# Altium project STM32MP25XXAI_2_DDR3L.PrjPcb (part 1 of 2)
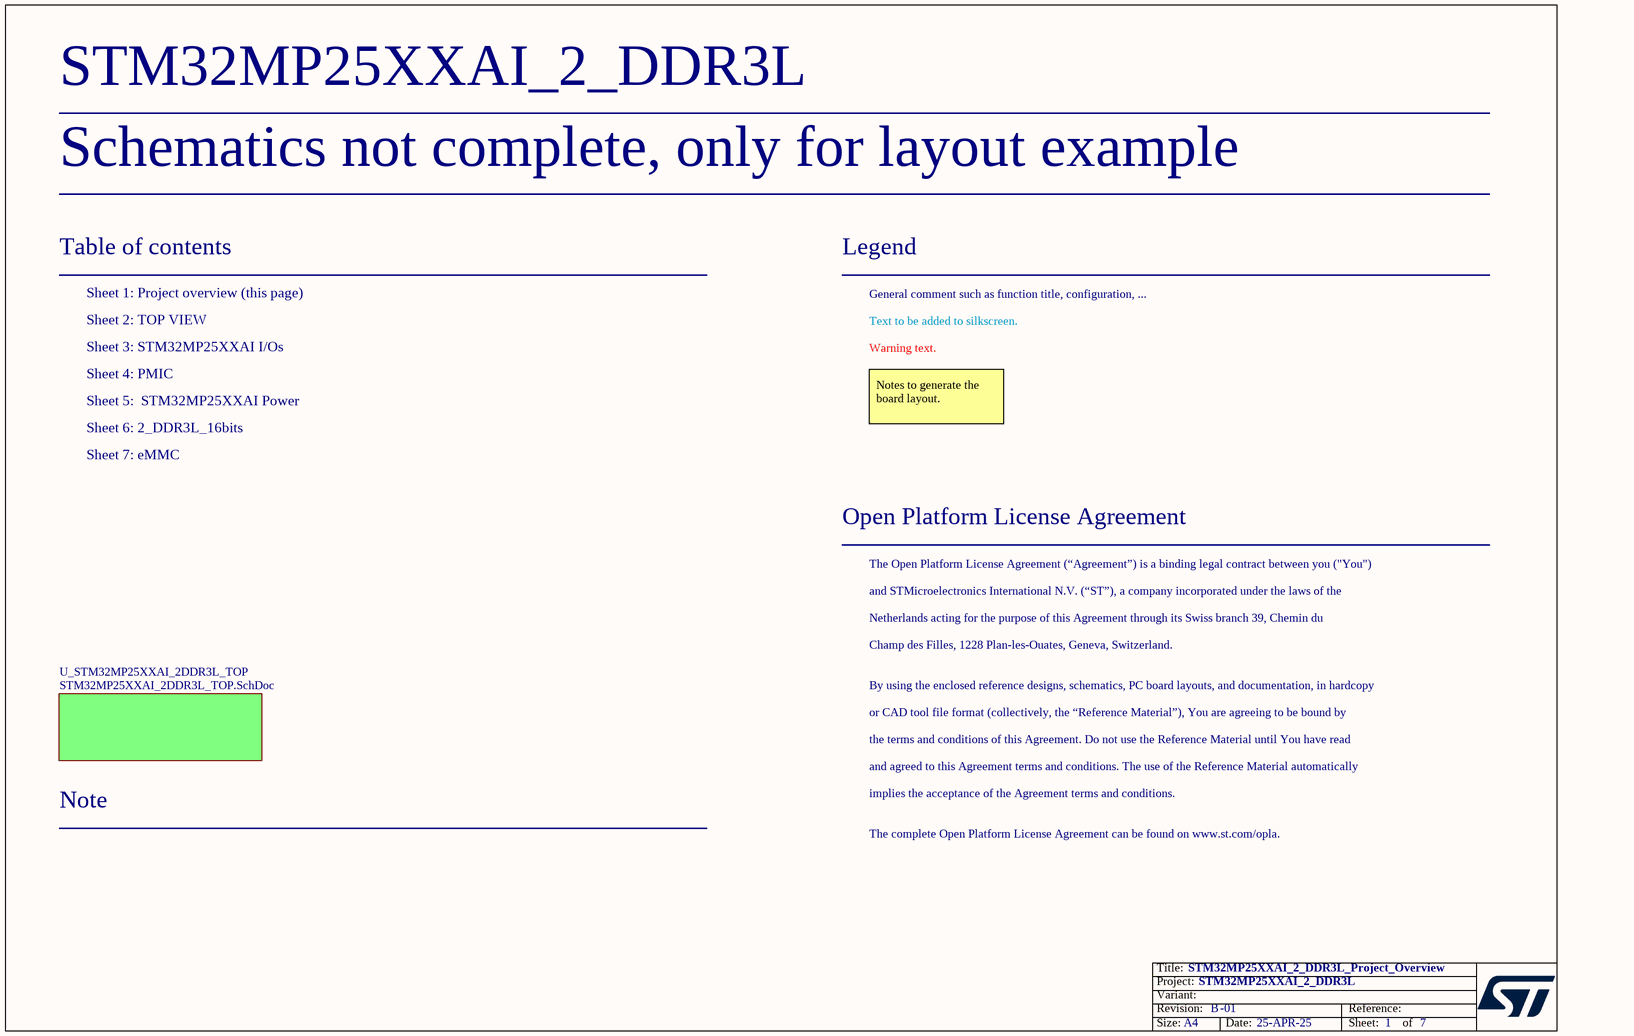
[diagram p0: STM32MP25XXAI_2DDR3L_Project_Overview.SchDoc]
Board_PCB_Revision: B; Board_Name: STM32MP25XXAI_2_DDR3L; Board_Document_Date: 25-APR-25; Board_Assembly_Revision: 01
7 sheets, 237 parts. Net scope: flat (ports and power ports of the same name join across sheets).
Board file: STM32MP25XXAI_2_DDR3L.PcbDoc
Sheets:
  STM32MP25XXAI_2DDR3L_Project_Overview.SchDoc
    U_STM32MP25XXAI_2DDR3L_TOP = STM32MP25XXAI_2DDR3L_TOP.SchDoc
      U_STM32MP25XXAI I_Os = STM32MP25XXAI I_Os.SchDoc
      U_PMIC = PMIC.SchDoc
      U_STM32MP25XXAI Power = STM32MP25XXAI Power.SchDoc
      U_eMMC = eMMC.SchDoc
      U_2_DDR3L_16bits = 2_DDR3L_16bits.SchDoc

## Sheet STM32MP25XXAI_2DDR3L_Project_Overview.SchDoc: STM32MP25XXAI_2_DDR3L_Project_Overview
size A4; Date: Not used; ApprovedBy: Not used; CheckedBy: Not used; Author: Not used; CompanyName: STMicroelectronics; DrawnBy: Not used; Engineer: Not used; Organization: Not used; Address1: Not used; Address2: Not used; Address3: Not used; Address4: Not used; DocumentNumber: 1; Revision: Not used; SheetNumber: 1; SheetTotal: 7

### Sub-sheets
U_STM32MP25XXAI_2DDR3L_TOP = STM32MP25XXAI_2DDR3L_TOP.SchDoc: no entries

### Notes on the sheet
- Schematics not complete, only for layout example
- Table of contents
- Sheet 1: Project overview (this page)
- Legend
- General comment such as function title, configuration, ...
- Sheet 2: TOP VIEW
- Sheet 3: STM32MP25XXAI I/Os
- Sheet 4: PMIC
- Text to be added to silkscreen.
- Warning text.
- Sheet 5:  STM32MP25XXAI Power
- Sheet 6: 2_DDR3L_16bits
- Notes to generate the board layout.
- Sheet 7: eMMC
- Open Platform License Agreement
- The Open Platform License Agreement (“Agreement”) is a binding legal contract between you ("You")
- and STMicroelectronics International N.V. (“ST”), a company incorporated under the laws of the
- Netherlands acting for the purpose of this Agreement through its Swiss branch 39, Chemin du
- Champ des Filles, 1228 Plan-les-Ouates, Geneva, Switzerland.
- By using the enclosed reference designs, schematics, PC board layouts, and documentation, in hardcopy
- or CAD tool file format (collectively, the “Reference Material”), You are agreeing to be bound by
- the terms and conditions of this Agreement. Do not use the Reference Material until You have read
- and agreed to this Agreement terms and conditions. The use of the Reference Material automatically
- Note
- implies the acceptance of the Agreement terms and conditions.
- The complete Open Platform License Agreement can be found on www.st.com/opla.

## Sheet STM32MP25XXAI_2DDR3L_TOP.SchDoc: TOP
size A4; Date: Not used; ApprovedBy: Not used; CheckedBy: Not used; Author: Not used; CompanyName: STMicroelectronics; DrawnBy: Not used; Engineer: Not used; Organization: Not used; Address1: Not used; Address2: Not used; Address3: Not used; Address4: Not used; DocumentNumber: 2; Revision: Not used; SheetNumber: 2; SheetTotal: 7
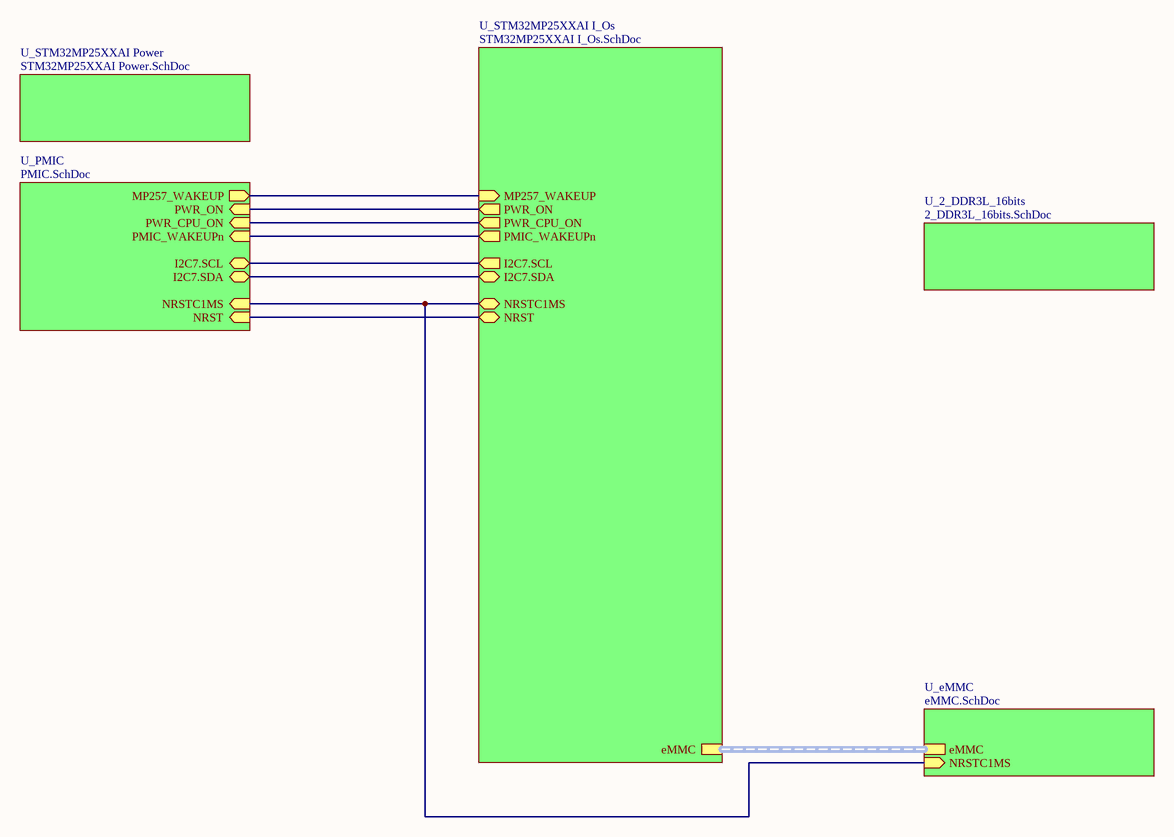
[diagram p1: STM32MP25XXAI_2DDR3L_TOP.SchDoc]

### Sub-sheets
U_2_DDR3L_16bits = 2_DDR3L_16bits.SchDoc: no entries
U_eMMC = eMMC.SchDoc: eMMC (harness eMMC), NRSTC1MS (in)
U_PMIC = PMIC.SchDoc: PMIC_WAKEUPn (in), NRST (in), I2C7.SCL (bidir), PWR_ON (in), PWR_CPU_ON (in), NRSTC1MS (in), I2C7.SDA (bidir), MP257_WAKEUP (out)
U_STM32MP25XXAI I_Os = STM32MP25XXAI I_Os.SchDoc: NRST (bidir), PWR_ON (out), NRSTC1MS (bidir), I2C7.SDA (bidir), I2C7.SCL (out), PWR_CPU_ON (out), MP257_WAKEUP (in), PMIC_WAKEUPn (out), eMMC (harness eMMC)
U_STM32MP25XXAI Power = STM32MP25XXAI Power.SchDoc: no entries

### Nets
(unnamed): sheet U_STM32MP25XXAI I_Os/NRST, sheet U_PMIC/NRST
(unnamed): sheet U_STM32MP25XXAI I_Os/PWR_ON, sheet U_PMIC/PWR_ON  [a separate net that carries the same name]
(unnamed): sheet U_STM32MP25XXAI I_Os/NRSTC1MS, sheet U_PMIC/NRSTC1MS, sheet U_eMMC/NRSTC1MS  [a separate net that carries the same name]
(unnamed): sheet U_STM32MP25XXAI I_Os/I2C7.SDA, sheet U_PMIC/I2C7.SDA  [a separate net that carries the same name]
(unnamed): sheet U_STM32MP25XXAI I_Os/I2C7.SCL, sheet U_PMIC/I2C7.SCL  [a separate net that carries the same name]
(unnamed): sheet U_STM32MP25XXAI I_Os/PWR_CPU_ON, sheet U_PMIC/PWR_CPU_ON  [a separate net that carries the same name]
(unnamed): sheet U_STM32MP25XXAI I_Os/MP257_WAKEUP, sheet U_PMIC/MP257_WAKEUP  [a separate net that carries the same name]
(unnamed): sheet U_STM32MP25XXAI I_Os/PMIC_WAKEUPn, sheet U_PMIC/PMIC_WAKEUPn  [a separate net that carries the same name]

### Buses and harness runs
harness sheet U_eMMC/eMMC = sheet U_STM32MP25XXAI I_Os/eMMC

## Sheet STM32MP25XXAI I_Os.SchDoc: STM32MP25XXAI  I/Os
size A3; Date: Not used; ApprovedBy: Not used; CheckedBy: Not used; Author: Not used; CompanyName: STMicroelectronics; DrawnBy: Not used; Engineer: Not used; Organization: Not used; Address1: Not used; Address2: Not used; Address3: Not used; Address4: Not used; DocumentNumber: 3; Revision: Not used; SheetNumber: 3; SheetTotal: 7
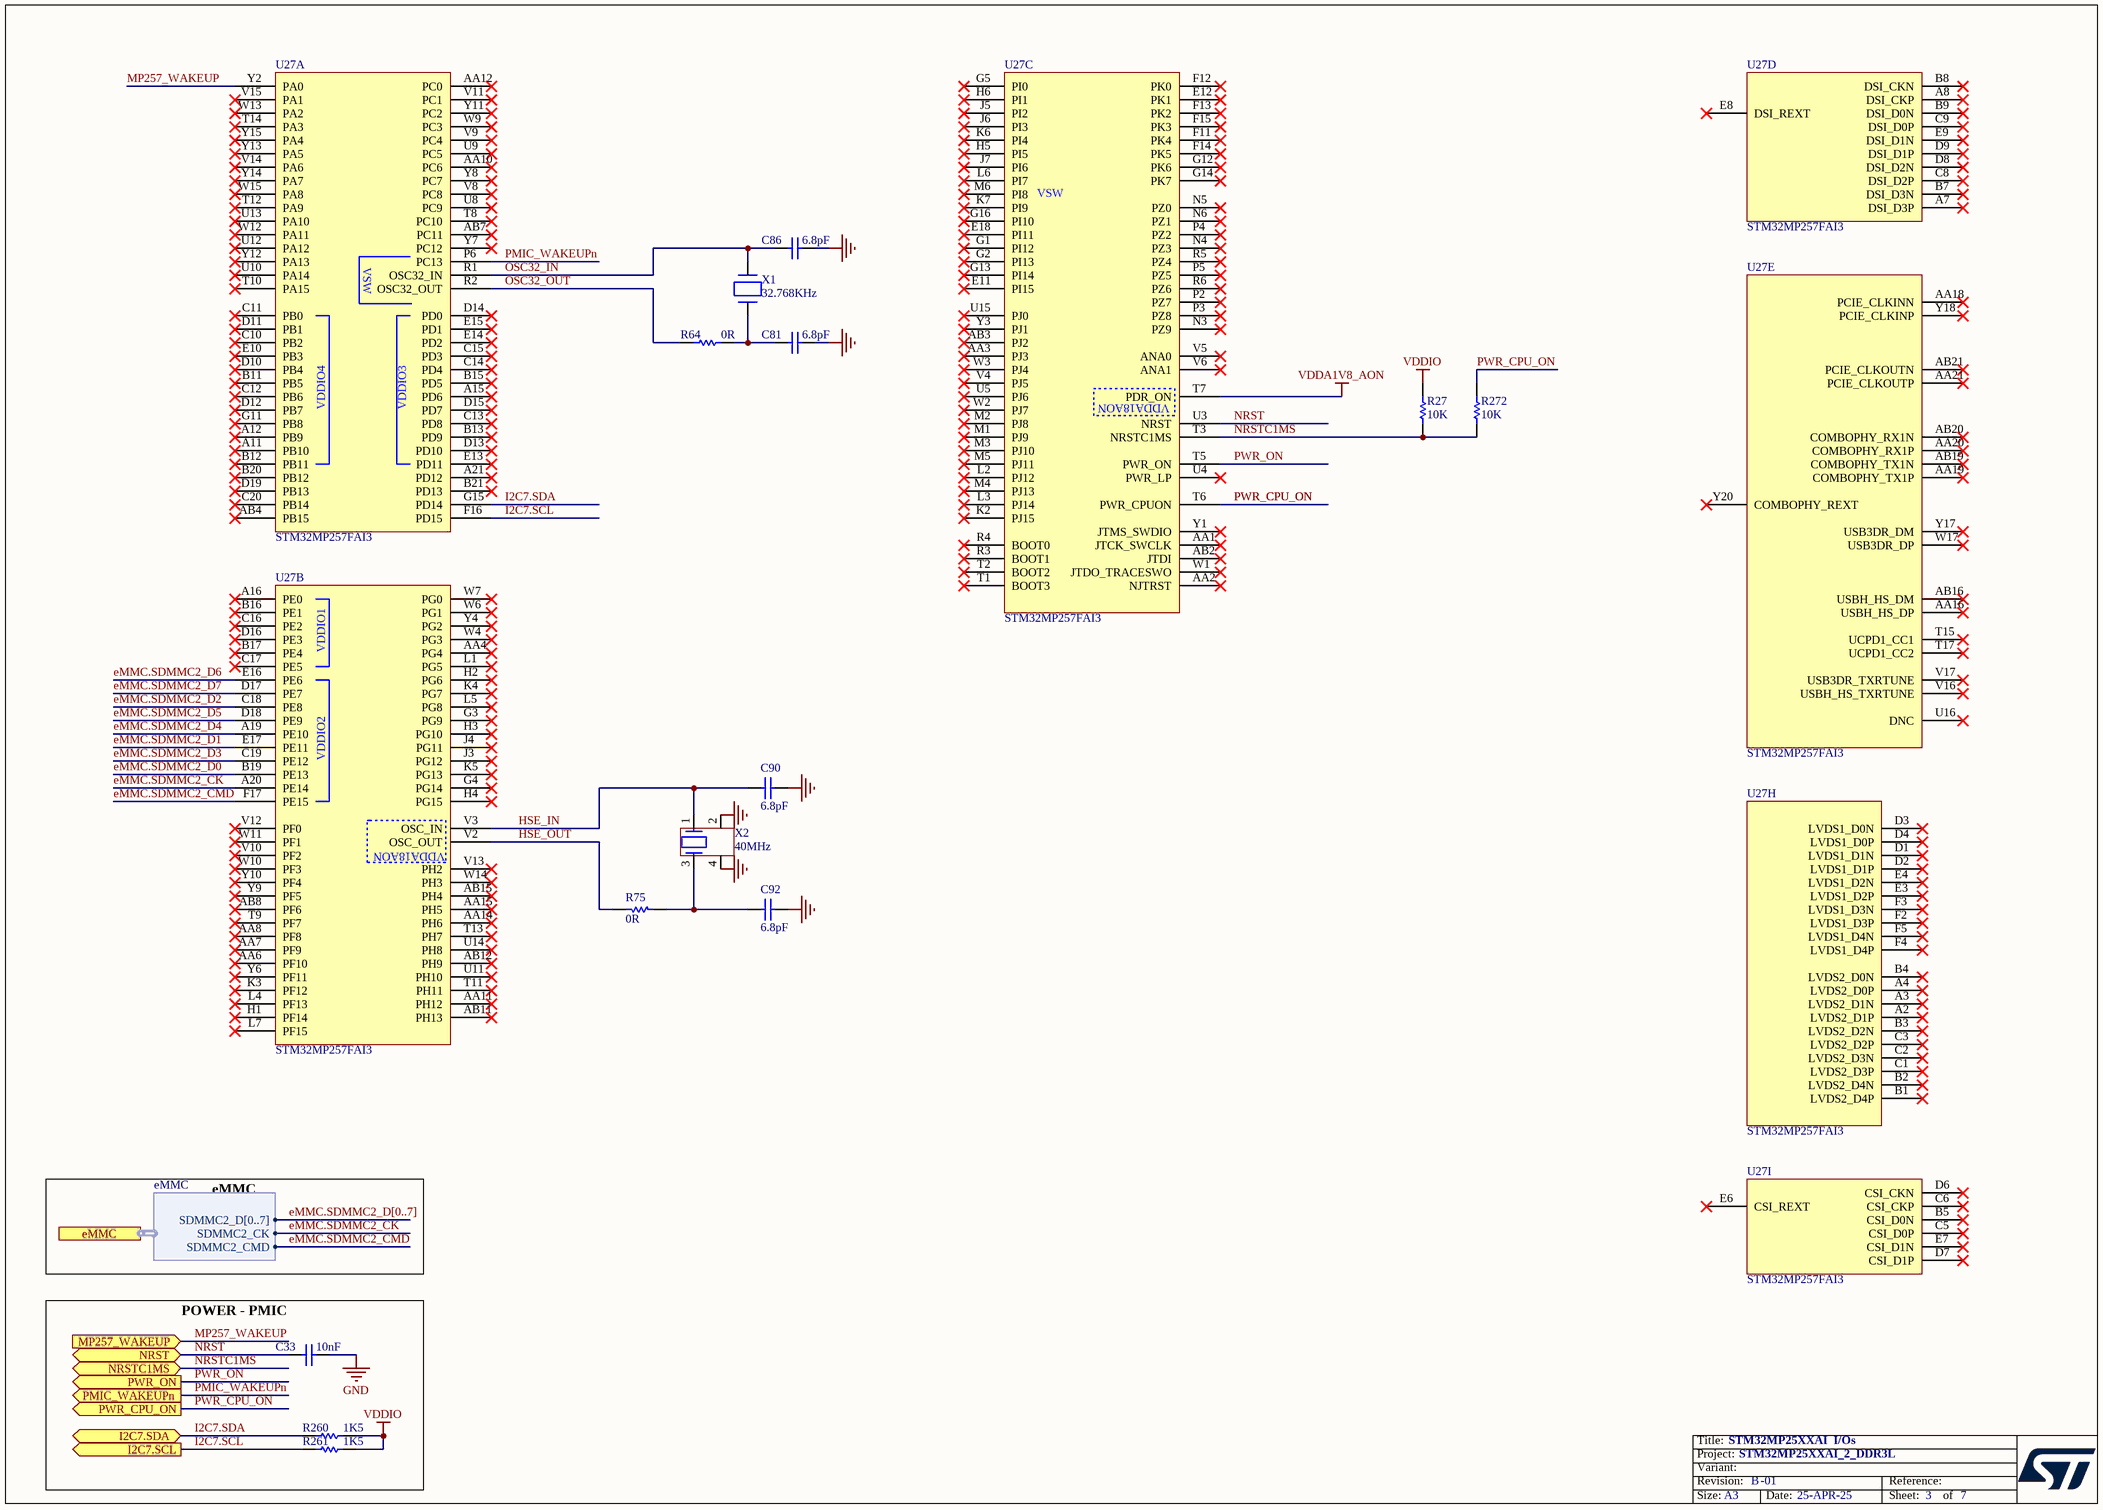
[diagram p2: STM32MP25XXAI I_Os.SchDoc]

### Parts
C33  value 10nF  [C0402]  (hidden comment: Capacitor)
C81  value 6.8pF  [C0402]  (hidden comment: Capacitor)
C86  value 6.8pF  [C0402]  (hidden comment: Capacitor)
C90  value 6.8pF  [C0402]  (hidden comment: Capacitor)
C92  value 6.8pF  [C0402]  (hidden comment: Capacitor)
R27  value 10K  [R0402]  (hidden comment: Resistor)
R64  value 0R  [R0402]
R75  value 0R  [R0402]
R260  value 1K5  [R0402]  (hidden comment: Resistor)
R261  value 1K5  [R0402]  (hidden comment: Resistor)
R272  value 10K  [R0402]  (hidden comment: Resistor)
U27  STM32MP257FAI3  [ICC_LFBGA436_18X18_P080_H1P70_STM32MP257_CODE-B0D1]  (parts A,B,C,D,E,H,I of 9)
X1  value 32.768KHz  [CRY_NX2012SA_2P]  (hidden comment: XTAL_2_PINS)
X2  value 40MHz  [CRY_NX1612SA_4P]  (hidden comment: XTAL_4_PINS)

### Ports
eMMC (harness eMMC), I2C7.SCL (out), I2C7.SDA (bidir), MP257_WAKEUP (in), NRST (bidir), NRSTC1MS (bidir), PMIC_WAKEUPn (out), PWR_CPU_ON (out), PWR_ON (out)

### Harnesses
eMMC: SDMMC2_CK, SDMMC2_CMD, SDMMC2_D[0..7]

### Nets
GND: C33.1 C81.2 C86.2 C90.1 C92.2 X2.2 X2.4
VDDA1V8_AON: U27.T7(PDR_ON)
VDDIO: R27.2 R260.2 R261.2
eMMC.SDMMC2_CK: U27.A20(PE14) ; port eMMC.SDMMC2_CK
eMMC.SDMMC2_CMD: U27.F17(PE15) ; port eMMC.SDMMC2_CMD
eMMC.SDMMC2_D0: U27.B19(PE13)
eMMC.SDMMC2_D1: U27.E17(PE11)
eMMC.SDMMC2_D2: U27.C18(PE8)
eMMC.SDMMC2_D3: U27.C19(PE12)
eMMC.SDMMC2_D4: U27.A19(PE10)
eMMC.SDMMC2_D5: U27.D18(PE9)
eMMC.SDMMC2_D6: U27.E16(PE6)
eMMC.SDMMC2_D7: U27.D17(PE7)
HSE_IN: C90.2 U27.V3(OSC_IN) X2.1
HSE_OUT: R75.2 U27.V2(OSC_OUT)
I2C7.SCL: R261.1 U27.F16(PD15) ; port I2C7.SCL
I2C7.SDA: R260.1 U27.G15(PD14) ; port I2C7.SDA
MP257_WAKEUP: U27.Y2(PA0) ; port MP257_WAKEUP
NRST: C33.2 U27.U3(NRST) ; port NRST
NRSTC1MS: R27.1 R272.1 U27.T3(NRSTC1MS) ; port NRSTC1MS
OSC32_IN: C86.1 U27.R1(OSC32_IN) X1.2(X2)
OSC32_OUT: R64.1 U27.R2(OSC32_OUT)
PMIC_WAKEUPn: U27.P6(PC13) ; port PMIC_WAKEUPn
PWR_CPU_ON: R272.2 U27.T6(PWR_CPUON) ; port PWR_CPU_ON
PWR_ON: U27.T5(PWR_ON) ; port PWR_ON
NetC81_1: C81.1 R64.2 X1.1(X1)
NetC92_1: C92.1 R75.1 X2.3

Not connected (* = marked no-connect by the designer): U27 A2(LVDS2_D1P)* A3(LVDS2_D1N)* A4(LVDS2_D0P)* A7(DSI_D3P)* A8(DSI_CKP)* A11(PB10)* A12(PB9)* A15(PD6)* A16(PE0)* A21(PD12)* AA1(JTCK_SWCLK)* AA2(NJTRST)* AA3(PJ3)* AA4(PG4)* AA6(PF10)* AA7(PF9)* AA8(PF8)* AA10(PC6)* AA11(PH12)* AA12(PC0)* AA14(PH6)* AA15(PH5)* AA16(USBH_HS_DP)* AA18(PCIE_CLKINN)* AA19(COMBOPHY_TX1P)* AA20(COMBOPHY_RX1P)* AA21(PCIE_CLKOUTP)* AB2(JTDI)* AB3(PJ2)* AB4(PB15)* AB7(PC11)* AB8(PF6)* AB11(PH13)* AB12(PH9)* AB15(PH4)* AB16(USBH_HS_DM)* AB19(COMBOPHY_TX1N)* AB20(COMBOPHY_RX1N)* AB21(PCIE_CLKOUTN)* B1(LVDS2_D4P)* B2(LVDS2_D4N)* B3(LVDS2_D2N)* B4(LVDS2_D0N)* B5(CSI_D0N)* B7(DSI_D3N)* B8(DSI_CKN)* B9(DSI_D0N)* B11(PB5)* B12(PB11)* B13(PD9)* B15(PD5)* B16(PE1)* B17(PE4)* B20(PB12)* B21(PD13)* C1(LVDS2_D3P)* C2(LVDS2_D3N)* C3(LVDS2_D2P)* C5(CSI_D0P)* C6(CSI_CKP)* C8(DSI_D2P)* C9(DSI_D0P)* C10(PB2)* C11(PB0)* C12(PB6)* C13(PD8)* C14(PD4)* C15(PD3)* C16(PE2)* C17(PE5)* C20(PB14)* D1(LVDS1_D1N)* D2(LVDS1_D1P)* D3(LVDS1_D0N)* D4(LVDS1_D0P)* D6(CSI_CKN)* D7(CSI_D1P)* D8(DSI_D2N)* D9(DSI_D1P)* D10(PB4)* D11(PB1)* D12(PB7)* D13(PD10)* D14(PD0)* D15(PD7)* D16(PE3)* D19(PB13)* E3(LVDS1_D2P)* E4(LVDS1_D2N)* E6(CSI_REXT)* E7(CSI_D1N)* E8(DSI_REXT)* E9(DSI_D1N)* E10(PB3)* E11(PI15)* E12(PK1)* E13(PD11)* E14(PD2)* E15(PD1)* E18(PI11)* F2(LVDS1_D3P)* F3(LVDS1_D3N)* F4(LVDS1_D4P)* F5(LVDS1_D4N)* F11(PK4)* F12(PK0)* F13(PK2)* F14(PK5)* F15(PK3)* G1(PI12)* G2(PI13)* G3(PG9)* G4(PG14)* G5(PI0)* G11(PB8)* G12(PK6)* G13(PI14)* G14(PK7)* G16(PI10)* H1(PF14)* H2(PG6)* H3(PG10)* H4(PG15)* H5(PI5)* H6(PI1)* J3(PG12)* J4(PG11)* J5(PI2)* J6(PI3)* J7(PI6)* K2(PJ15)* K3(PF12)* K4(PG7)* K5(PG13)* K6(PI4)* K7(PI9)* L1(PG5)* L2(PJ12)* L3(PJ14)* L4(PF13)* L5(PG8)* L6(PI7)* L7(PF15)* M1(PJ9)* M2(PJ8)* M3(PJ10)* M4(PJ13)* M5(PJ11)* M6(PI8)* N3(PZ9)* N4(PZ3)* N5(PZ0)* N6(PZ1)* P2(PZ7)* P3(PZ8)* P4(PZ2)* P5(PZ5)* R3(BOOT1)* R4(BOOT0)* R5(PZ4)* R6(PZ6)* T1(BOOT3)* T2(BOOT2)* T8(PC10)* T9(PF7)* T10(PA15)* T11(PH11)* T12(PA9)* T13(PH7)* T14(PA3)* T15(UCPD1_CC1)* T17(UCPD1_CC2)* U4(PWR_LP)* U5(PJ6)* U8(PC9)* U9(PC5)* U10(PA14)* U11(PH10)* U12(PA12)* U13(PA10)* U14(PH8)* U15(PJ0)* U16(DNC)* V4(PJ5)* V5(ANA0)* V6(ANA1)* V8(PC8)* V9(PC4)* V10(PF2)* V11(PC1)* V12(PF0)* V13(PH2)* V14(PA6)* V15(PA1)* V16(USBH_HS_TXRTUNE)* V17(USB3DR_TXRTUNE)* W1(JTDO_TRACESWO)* W2(PJ7)* W3(PJ4)* W4(PG3)* W6(PG1)* W7(PG0)* W9(PC3)* W10(PF3)* W11(PF1)* W12(PA11)* W13(PA2)* W14(PH3)* W15(PA8)* W17(USB3DR_DP)* Y1(JTMS_SWDIO)* Y3(PJ1)* Y4(PG2)* Y6(PF11)* Y7(PC12)* Y8(PC7)* Y9(PF5)* Y10(PF4)* Y11(PC2)* Y12(PA13)* Y13(PA5)* Y14(PA7)* Y15(PA4)* Y17(USB3DR_DM)* Y18(PCIE_CLKINP)* Y20(COMBOPHY_REXT)*

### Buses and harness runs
bus eMMC.SDMMC2_D[0..7]

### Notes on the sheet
- eMMC
- POWER - PMIC

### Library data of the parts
C33 = MCD-00011: Capacitor, MLCC, 10nF, 16V, X7R, 10%, 0402, T=0.5mm; Manufacturer_Part_Number: CC0402KRX7R7BB103; Manufacturer: YAGEO; Part_Preference: Recommended; Provided_By: SUBCO; Initial_Board_Reference: MB1274; Order_Code_RS: 3019275; Component_Country_Of_Origin: China; ID: 2469; ShowFields: YES
C81 C86 = MCD-00674: Capacitor, MLCC, 6.8pF, 50V, NPO, +-0.25pF, 0402, T=0.5mm; Manufacturer_Part_Number: CC0402CRNPO9BN6R8; Manufacturer: YAGEO; Part_Preference: Recommended; Provided_By: SUBCO; Initial_Board_Reference: MB1319; Path: ws/MCD_ApplicationBoards/Lists/MCDPARTSdatabase; Item Type: Item; Component_Country_Of_Origin: China; ID: 3068; ShowFields: YES
C90 C92 = MCD-00674: Capacitor, MLCC, 6.8pF, 50V, NPO, +-0.25pF, 0402, T=0.5mm; Manufacturer_Part_Number: CC0402CRNPO9BN6R8; Manufacturer: YAGEO; Part_Preference: Recommended; Provided_By: SUBCO; Initial_Board_Reference: MB1319; Component_Country_Of_Origin: China; ID: 3068; ShowFields: YES
R27 R272 = MCD-00053: Resistor,10K,0402,1%,1/16W; BMS_Part_Number: 9131590; Part_Preference: Recommended; Manufacturer: YAGEO; Manufacturer_Part_Number: RC0402FR-0710KL; Order_Code_RS: 9239359; Component_Country_Of_Origin: China; ID: 2539; ShowFields: YES
R64 R75 = MCD-00052: Resistor,0R,0402,5%,1/16W; Manufacturer_Part_Number: RC0402JR-070RL; Manufacturer: YAGEO; Part_Preference: Recommended; Provided_By: SUBCO; Initial_Board_Reference: mb1274; Order_Code_RS: 9232516RL; Component_Country_Of_Origin: China; ID: 2540; ShowFields: YES
R260 R261 = MCD-00068: Resistor,1K5,0402,1%,1/16W; Part_Preference: Recommended; Manufacturer: YAGEO; Manufacturer_Part_Number: RC0402FR-071K5L; Order_Code_RS: 9239251; Component_Country_Of_Origin: China; ID: 2524; ShowFields: YES
U27 = MCD-02000: MPU, ARM Cortex-A35 + M33 32-bit MPU, 808KB RAM, With Crypto; Part_Type: IC; Part_Preference: Recommended; Manufacturer: STMICROELECTRONICS; Manufacturer_HQ_COO: EU; Component_Country_Of_Origin: Unknown; ShowFields: YES; ID: 4100
X1 = MCD-01479: Crystal, 32.768kHz, 6pF, +/-20ppm, 80K, 2.05x1.2mm; BMS_Part_Number: 9157049; Part_Type: Crystal_Osc; Part_Preference: Recommended; Manufacturer: NDK; Manufacturer_Part_Number: NX2012SA-32.768KHZ-EXS00A-MU00527; Component_Country_Of_Origin: Unknown; ShowFields: YES; ID: 3579
X2 = MCD-02344: Crystal, 40MHz, 6pF, +/-20ppm, 80R, 1.6x1.2mm; Part_Type: Crystal_Osc; Part_Preference: Not recommended; Manufacturer: NDK; Manufacturer_Part_Number: NX1612SA-40MHZ-EXS00A-CS13836; Component_Country_Of_Origin: Unknown; ShowFields: YES; ID: 4450

## Sheet PMIC.SchDoc: PMIC
size A3; Date: Not used; ApprovedBy: Not used; CheckedBy: Not used; Author: Not used; CompanyName: STMicroelectronics; DrawnBy: Not used; Engineer: Not used; Organization: Not used; Address1: Not used; Address2: Not used; Address3: Not used; Address4: Not used; DocumentNumber: 4; Revision: Not used; SheetNumber: 4; SheetTotal: 7
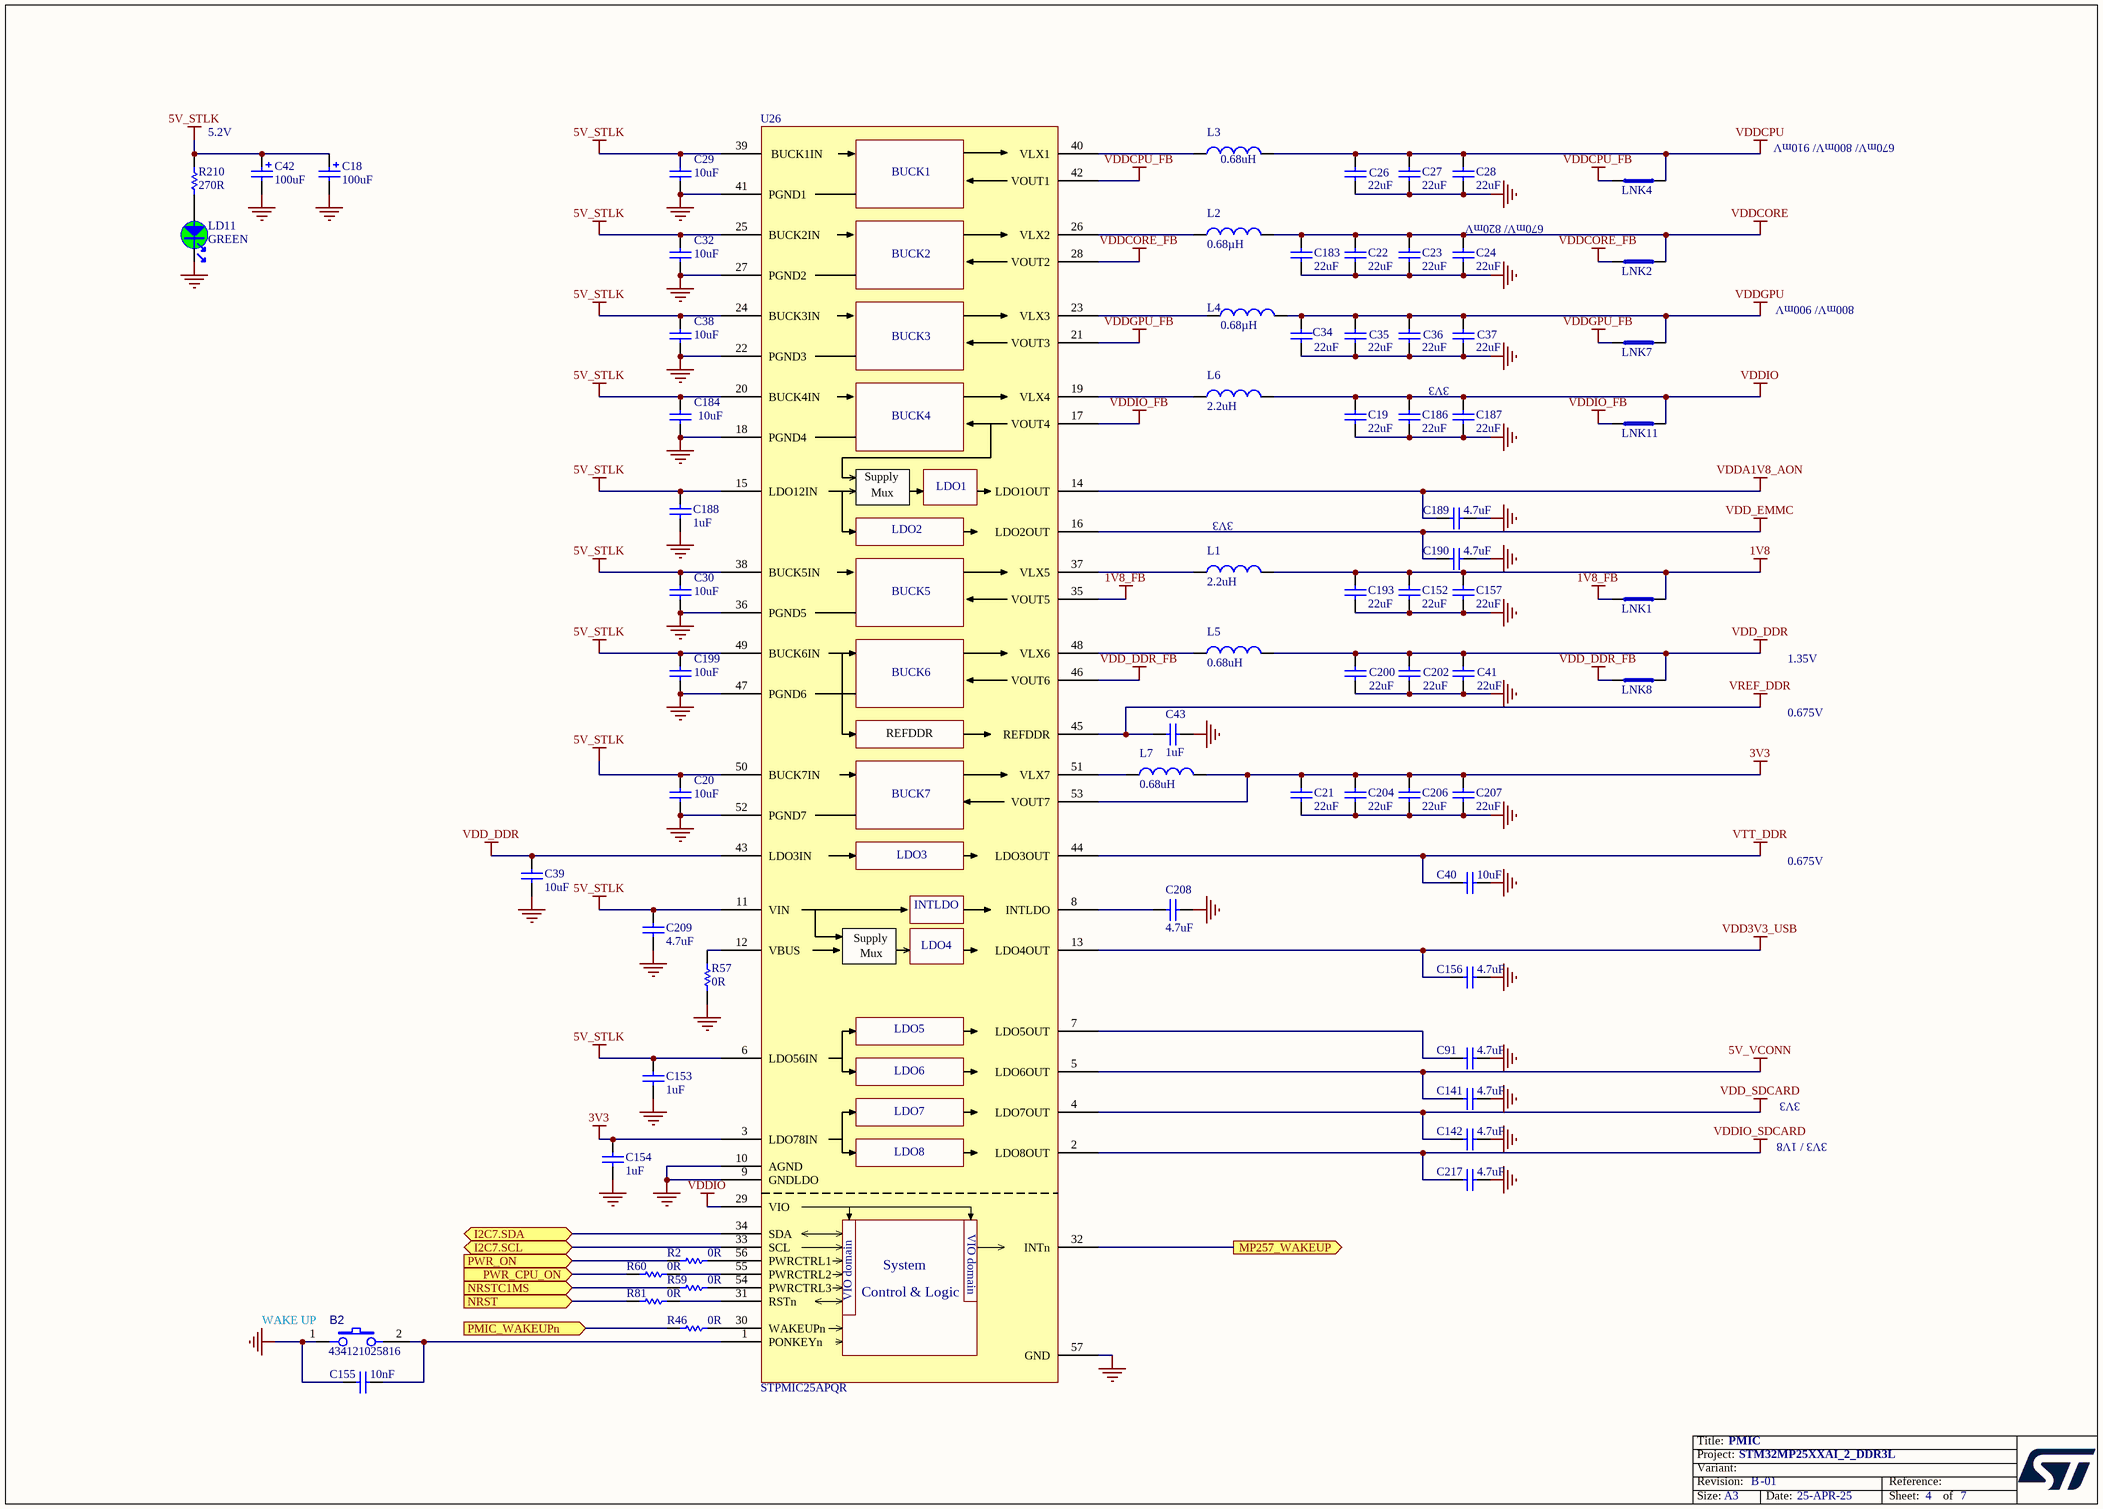
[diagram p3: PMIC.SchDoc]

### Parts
B2  value 434121025816  [SWI_WE_434121025816]  (hidden comment: SW_PUSH_SMD_2P)
C18  value 100uF  [CPOL_TCJ-B_1210_H210]  (hidden comment: Cap_POL_TANA)
C19  value 22uF  [C0805]  (hidden comment: Capacitor)
C20  value 10uF  [C0603]  (hidden comment: Capacitor)
C21  value 22uF  [C0805]  (hidden comment: Capacitor)
C22  value 22uF  [C0603]  (hidden comment: Capacitor)
C23  value 22uF  [C0603]  (hidden comment: Capacitor)
C24  value 22uF  [C0603]  (hidden comment: Capacitor)
C26  value 22uF  [C0603]  (hidden comment: Capacitor)
C27  value 22uF  [C0603]  (hidden comment: Capacitor)
C28  value 22uF  [C0603]  (hidden comment: Capacitor)
C29  value 10uF  [C0603]  (hidden comment: Capacitor)
C30  value 10uF  [C0603]  (hidden comment: Capacitor)
C32  value 10uF  [C0603]  (hidden comment: Capacitor)
C34  value 22uF  [C0603]  (hidden comment: Capacitor)
C35  value 22uF  [C0603]  (hidden comment: Capacitor)
C36  value 22uF  [C0603]  (hidden comment: Capacitor)
C37  value 22uF  [C0603]  (hidden comment: Capacitor)
C38  value 10uF  [C0603]  (hidden comment: Capacitor)
C39  value 10uF  [C0402]  (hidden comment: Capacitor)
C40  value 10uF  [C0402]  (hidden comment: Capacitor)
C41  value 22uF  [C0603]  (hidden comment: Capacitor)
C42  value 100uF  [CPOL_TCJ-B_1210_H210]  (hidden comment: Cap_POL_TANA)
C43  value 1uF  [C0402]  (hidden comment: Capacitor)
C91  value 4.7uF  [C0402]  (hidden comment: Capacitor)
C141  value 4.7uF  [C0402]  (hidden comment: Capacitor)
C142  value 4.7uF  [C0402]  (hidden comment: Capacitor)
C152  value 22uF  [C0805]  (hidden comment: Capacitor)
C153  value 1uF  [C0402]  (hidden comment: Capacitor)
C154  value 1uF  [C0402]  (hidden comment: Capacitor)
C155  value 10nF  [C0402]  (hidden comment: Capacitor)
C156  value 4.7uF  [C0402]  (hidden comment: Capacitor)
C157  value 22uF  [C0805]  (hidden comment: Capacitor)
C183  value 22uF  [C0603]  (hidden comment: Capacitor)
C184  value 10uF  [C0603]  (hidden comment: Capacitor)
C186  value 22uF  [C0805]  (hidden comment: Capacitor)
C187  value 22uF  [C0805]  (hidden comment: Capacitor)
C188  value 1uF  [C0402]  (hidden comment: Capacitor)
C189  value 4.7uF  [C0402]  (hidden comment: Capacitor)
C190  value 4.7uF  [C0402]  (hidden comment: Capacitor)
C193  value 22uF  [C0805]  (hidden comment: Capacitor)
C199  value 10uF  [C0603]  (hidden comment: Capacitor)
C200  value 22uF  [C0603]  (hidden comment: Capacitor)
C202  value 22uF  [C0603]  (hidden comment: Capacitor)
C204  value 22uF  [C0805]  (hidden comment: Capacitor)
C206  value 22uF  [C0805]  (hidden comment: Capacitor)
C207  value 22uF  [C0805]  (hidden comment: Capacitor)
C208  value 4.7uF  [C0402]  (hidden comment: Capacitor)
C209  value 4.7uF  [C0402]  (hidden comment: Capacitor)
C217  value 4.7uF  [C0402]  (hidden comment: Capacitor)
L1  value 2.2uH  [IND_2016_MURATA_LQM2MPN2R2NG0]  (hidden comment: Inductor)
L2  value 0.68µH  [IND_2520_TOKO_DFE252012P]  (hidden comment: Inductor)
L3  value 0.68uH  [IND_2016_MURATA_LQM2MPN2R2NG0]  (hidden comment: Inductor)
L4  value 0.68µH  [IND_2520_TOKO_DFE252012P]  (hidden comment: Inductor)
L5  value 0.68uH  [IND_2016_MURATA_LQM2MPN2R2NG0]  (hidden comment: Inductor)
L6  value 2.2uH  [IND_2016_MURATA_LQM2MPN2R2NG0]  (hidden comment: Inductor)
L7  value 0.68uH  [IND_2016_MURATA_LQM2MPN2R2NG0]  (hidden comment: Inductor)
LD11  value GREEN  [LED_0603_OSRAM_LG-Q396-PS-35_GREEN_1A2K_H0P4]  (hidden comment: LED_green)
LNK1  link_200  [LINK200]  (value not drawn)  (no BOM)
LNK2  link_200  [LINK200]  (value not drawn)  (no BOM)
LNK4  link_200  [LINK200]  (value not drawn)  (no BOM)
LNK7  link_200  [LINK200]  (value not drawn)  (no BOM)
LNK8  link_200  [LINK200]  (value not drawn)  (no BOM)
LNK11  link_200  [LINK200]  (value not drawn)  (no BOM)
R2  value 0R  [R0402]
R46  value 0R  [R0402]
R57  value 0R  [R0402]
R59  value 0R  [R0402]
R60  value 0R  [R0402]
R81  value 0R  [R0402]
R210  value 270R  [R0402]  (hidden comment: Resistor)
U26  STPMIC25APQR  [ICC_QFN56-EPAD_6P5X6P5_P040]

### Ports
I2C7.SCL (bidir), I2C7.SDA (bidir), MP257_WAKEUP (out), NRST (in), NRSTC1MS (in), PMIC_WAKEUPn (in), PWR_CPU_ON (in), PWR_ON (in)

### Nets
1V8: C152.2 C157.2 C193.2 L1.2 LNK1.2
1V8_FB: LNK1.1 U26.35(VOUT5)
3V3: C21.2 C154.2 C204.2 C206.2 C207.2 L7.2 U26.3(LDO78IN) U26.53(VOUT7)
5V_STLK: C18.1 C20.2 C29.2 C30.2 C32.2 C38.2 C42.1 C153.2 C184.2 C188.2 C199.2 C209.2 R210.1 U26.6(LDO56IN) U26.11(VIN) U26.15(LDO12IN) U26.20(BUCK4IN) U26.24(BUCK3IN) U26.25(BUCK2IN) U26.38(BUCK5IN) U26.39(BUCK1IN) U26.49(BUCK6IN) U26.50(BUCK7IN)
5V_VCONN: C141.1 U26.5(LDO6OUT)
GND: B2.1 C18.2 C19.1 C20.1 C21.1 C22.1 C23.1 C24.1 C26.1 C27.1 C28.1 C29.1 C30.1 C32.1 C34.1 C35.1 C36.1 C37.1 C38.1 C39.1 C40.1 C41.1 C42.2 C43.1 C91.2 C141.2 C142.2 C152.1 C153.1 C154.1 C155.1 C156.1 C157.1 C183.1 C184.1 C186.1 C187.1 C188.1 C189.1 C190.2 C193.1 C199.1 C200.1 C202.1 C204.1 C206.1 C207.1 C208.2 C209.1 C217.2 LD11.2 R57.1 U26.9(GNDLDO) U26.10(AGND) U26.18(PGND4) U26.22(PGND3) U26.27(PGND2) U26.36(PGND5) U26.41(PGND1) U26.47(PGND6) U26.52(PGND7) U26.57(GND)
VDD3V3_USB: C156.2 U26.13(LDO4OUT)
VDD_DDR: C39.2 C41.2 C200.2 C202.2 L5.2 LNK8.2 U26.43(LDO3IN)
VDD_DDR_FB: LNK8.1 U26.46(VOUT6)
VDD_EMMC: C190.1 U26.16(LDO2OUT)
VDD_SDCARD: C142.1 U26.4(LDO7OUT)
VDDA1V8_AON: C189.2 U26.14(LDO1OUT)
VDDCORE: C22.2 C23.2 C24.2 C183.2 L2.2 LNK2.2
VDDCORE_FB: LNK2.1 U26.28(VOUT2)
VDDCPU: C26.2 C27.2 C28.2 L3.2 LNK4.1
VDDCPU_FB: LNK4.2 U26.42(VOUT1)
VDDGPU: C34.2 C35.2 C36.2 C37.2 L4.2 LNK7.2
VDDGPU_FB: LNK7.1 U26.21(VOUT3)
VDDIO: C19.2 C186.2 C187.2 L6.2 LNK11.2 U26.29(VIO)
VDDIO_FB: LNK11.1 U26.17(VOUT4)
VDDIO_SDCARD: C217.1 U26.2(LDO8OUT)
VREF_DDR: C43.2 U26.45(REFDDR)
VTT_DDR: C40.2 U26.44(LDO3OUT)
I2C7.SCL: U26.33(SCL) ; port I2C7.SCL
I2C7.SDA: U26.34(SDA) ; port I2C7.SDA
MP257_WAKEUP: U26.32(INTn) ; port MP257_WAKEUP
NRST: R81.1 ; port NRST
NRSTC1MS: R59.1 ; port NRSTC1MS
PMIC_WAKEUPn: R46.1 ; port PMIC_WAKEUPn
PWR_CPU_ON: R60.1 ; port PWR_CPU_ON
PWR_ON: R2.1 ; port PWR_ON
NetB2_2: B2.2 C155.2 U26.1(PONKEYn)
NetC91_1: C91.1 U26.7(LDO5OUT)
NetC208_1: C208.1 U26.8(INTLDO)
NetL1_1: L1.1 U26.37(VLX5)
NetL2_1: L2.1 U26.26(VLX2)
NetL3_1: L3.1 U26.40(VLX1)
NetL4_1: L4.1 U26.23(VLX3)
NetL5_1: L5.1 U26.48(VLX6)
NetL6_1: L6.1 U26.19(VLX4)
NetL7_1: L7.1 U26.51(VLX7)
NetLD11_1: LD11.1 R210.2
NetR2_2: R2.2 U26.56(PWRCTRL1)
NetR46_2: R46.2 U26.30(WAKEUPn)
NetR57_2: R57.2 U26.12(VBUS)
NetR59_2: R59.2 U26.54(PWRCTRL3)
NetR60_2: R60.2 U26.55(PWRCTRL2)
NetR81_2: R81.2 U26.31(RSTn)

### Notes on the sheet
- 5.2V
- 670mV/ 800mV/ 910mV
- (near C24) 670mV/ 820mV
- 800mV/ 900mV
- 3V3
- (near L1) 3V3
- 1.35V
- 0.675V
- 3V3 / 1V8
- (near B2) WAKE UP

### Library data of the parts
B2 = MCD-03492: Switch tactile, SPST-NO, 50mA, 12V, 6x3.8mm; Part_Type: Misc; Part_Preference: Recommended; Manufacturer: WURTH ELEKTRONIK; Order_Code_RS: 1867991; Component_Country_Of_Origin: China; ShowFields: YES; ID: 5608
C18 C42 = MCD-01796: Capacitor, Tantalum, 100uF, 6V3, 40mR, +/-20%,  Type_B (3528 metric), T=1.9mm; Part_Preference: Recommended; Manufacturer: AVX; Manufacturer_Part_Number: TCJB107M006R0040; Component_Country_Of_Origin: Czech Republic; ShowFields: YES; ID: 3896
C19 C21 C152 C157 C186 C187 C193 C204 C206 C207 = MCD-03139: Capacitor, MLCC, 22uF, 10V, X5R, +/-20%, 0805, T=1,25mm; Part_Preference: Recommended; Manufacturer: MURATA; Manufacturer_Part_Number: GRM21BR61A226ME51L; ShowFields: YES; ID: 5255; Component_Country_Of_Origin: China, Japan
C20 C29 C30 C32 C38 C184 C199 = MCD-00099: Capacitor, MLCC, 10uF, 10V, X5R, +/-10%, 0603, T=0,8mm; Manufacturer_Part_Number: GRM188R61A106KE69D; Manufacturer: MURATA; Part_Preference: Recommended; Partial_Alternate_Internal_Part_Number: MCD-03152; Order_Code_RS: 2494233; Component_Country_Of_Origin: Japan°°; ID: 2770; ShowFields: YES
C22-C24 C26 C34-C37 C41 C200 C202 = MCD-00100: Capacitor, MLCC, 22uF, 6V3, X5R, +/-20%, 0603, T=0,8mm; Manufacturer_Part_Number: GRM188R60J226MEA0J; Manufacturer: MURATA; Part_Preference: Recommended; Component_Country_Of_Origin: Japan°°; ID: 2766; ShowFields: YES
C27 C28 C183 = MCD-00100: Capacitor, MLCC, 22uF, 6V3, X5R, +/-20%, 0603, T=0,8mm; Part_Preference: Recommended; Manufacturer: MURATA; Manufacturer_Part_Number: GRM188R60J226MEA0J; Component_Country_Of_Origin: Japan°°; ID: 2766; ShowFields: YES
C39 = MCD-03140: Capacitor, MLCC, 10uF, 6.3V, X5R, +/-20%, 0402, T=0.5mm; Part_Preference: Recommended; Manufacturer: MURATA; Manufacturer_Part_Number: GRM155R60J106ME05D; ShowFields: YES; ID: 5256
C40 = MCD-03140: Capacitor, MLCC, 10uF, 6.3V, X5R, +/-20%, 0402, T=0.5mm; Part_Preference: Recommended; Manufacturer: MURATA; Manufacturer_Part_Number: GRM155R60J106ME05D; ShowFields: YES; ID: 5256; Component_Country_Of_Origin: China, Japan
C43 C153 C154 C188 = MCD-00095: Capacitor, MLCC, 1uF, 25V, X5R, +/-10%, 0402, T=0.5mm; Part_Preference: Recommended; Manufacturer: MURATA; Manufacturer_Part_Number: GRM155R61E105KA12; Partial_Alternate_Internal_Part_Number: MCD-04188; Order_Code_RS: 2218855; Component_Country_Of_Origin: Japan°°; ShowFields: YES; ID: 2772
C91 C141 C142 C156 C189 C190 C208 C209 C217 = MCD-01356: Capacitor, MLCC, 4.7uF, 6V3, X5R, +/-20%, 0402, T=0.5mm; Manufacturer_Part_Number: GRM155R60J475ME47; Manufacturer: MURATA; Part_Preference: Recommended; Order_Code_RS: 814-5230; Component_Country_Of_Origin: Japan°°; ShowFields: YES; ID: 3456
C155 = MCD-02198: Capacitor, MLCC, 10nF, 50V, X7R, +/-10%, 0402, T=0.5mm; Manufacturer_Part_Number: CC0402KRX7R9BB103; Manufacturer: YAGEO; Part_Preference: Recommended; Order_Code_RS: 6169644; Component_Country_Of_Origin: China; ShowFields: YES; ID: 4298
L1 L6 = MCD-03143: Inductor, 2.2uH, +/-20%, Itemp= 1700mA, Isat= 2400mA, 0R140, 0806, T=1mm; Part_Preference: Recommended; Manufacturer: MURATA; Manufacturer_Part_Number: DFE201610E-2R2M=P2; ShowFields: YES; ID: 5259; Component_Country_Of_Origin: Vietnam
L2 L4 = MCD-03142: Inductor, 0.68uH, +/-20%, Itemp= 3900mA, Isat= 5400mA, 0R031, 1008, T=1.2mm; Part_Preference: Recommended; Manufacturer: MURATA; Manufacturer_Part_Number: DFE252012F-R68M=P2; ShowFields: YES; ID: 5258; Component_Country_Of_Origin: Vietnam
L3 L5 L7 = MCD-03141: Inductor, 0.68uH, +/-20%, Itemp= 3100mA, Isat= 4300mA, 0R043, 0806, T=1mm; Part_Preference: Recommended; Manufacturer: MURATA; Manufacturer_Part_Number: DFE201610E-R68M=P2; ShowFields: YES; ID: 5257; Component_Country_Of_Origin: Vietnam
LD11 = MCD-00588: LED Green, 0603 SMD, Forward Voltage Typ=2V, Max=2.5V; Part_Type: Display; Manufacturer_Part_Number: LG Q396-PS-35; Manufacturer: OSRAM OPTO SEMICONDUCTORS; Alternate_Manufacturer_Part_Number: VLMTG1300-GS08; Alternate_Manufacturer: VISHAY SEMICONDUCTOR OPTO DIVISION; Alternate_Internal_Part_Number: MCD-02400; Part_Preference: Recommended; Partial_Alternate_Internal_Part_Number: MCD-02400, MCD-03155, MCD-02901; Provided_By: SUBCO; Component_Country_Of_Origin: Unknown; ID: 3155; ShowFields: YES
LNK1 LNK2 LNK4 LNK7 LNK8 LNK11 = MCD-02777: Track link on PCB 200um width for layout routing; Part_Preference: Recommended; Part_Type: Misc; ID: 4889; ShowFields: YES; Component_Country_Of_Origin: Unknown
R2 R46 R57 R59 R60 R81 = MCD-00052: Resistor,0R,0402,5%,1/16W; Manufacturer_Part_Number: RC0402JR-070RL; Manufacturer: YAGEO; Part_Preference: Recommended; ECCN_US: EAR99; ECCN_EU: NEC; Provided_By: SUBCO; Initial_Board_Reference: mb1274; Order_Code_RS: 9232516RL; Component_Country_Of_Origin: China; ID: 2540; ShowFields: YES
R210 = MCD-00441: Resistor,270R,0402,1%,1/16W; Manufacturer_Part_Number: RC0402FR-07270RL; Manufacturer: YAGEO; Part_Preference: Recommended; Provided_By: SUBCO; ECCN_US: EAR99; ECCN_EU: NEC; Component_Country_Of_Origin: China; ID: 2838; ShowFields: YES
U26 = MCD-03000: STPMIC2; Part_Type: IC; Part_Preference: Recommended; Manufacturer: STMICROELECTRONICS; Component_Country_Of_Origin: Unknown; ShowFields: YES; ID: 5116

## Sheet STM32MP25XXAI Power.SchDoc: STM32MP25XXAI Power
size A3; Date: Not used; ApprovedBy: Not used; CheckedBy: Not used; Author: Not used; CompanyName: STMicroelectronics; DrawnBy: Not used; Engineer: Not used; Organization: Not used; Address1: Not used; Address2: Not used; Address3: Not used; Address4: Not used; DocumentNumber: 5; Revision: Not used; SheetNumber: 5; SheetTotal: 7
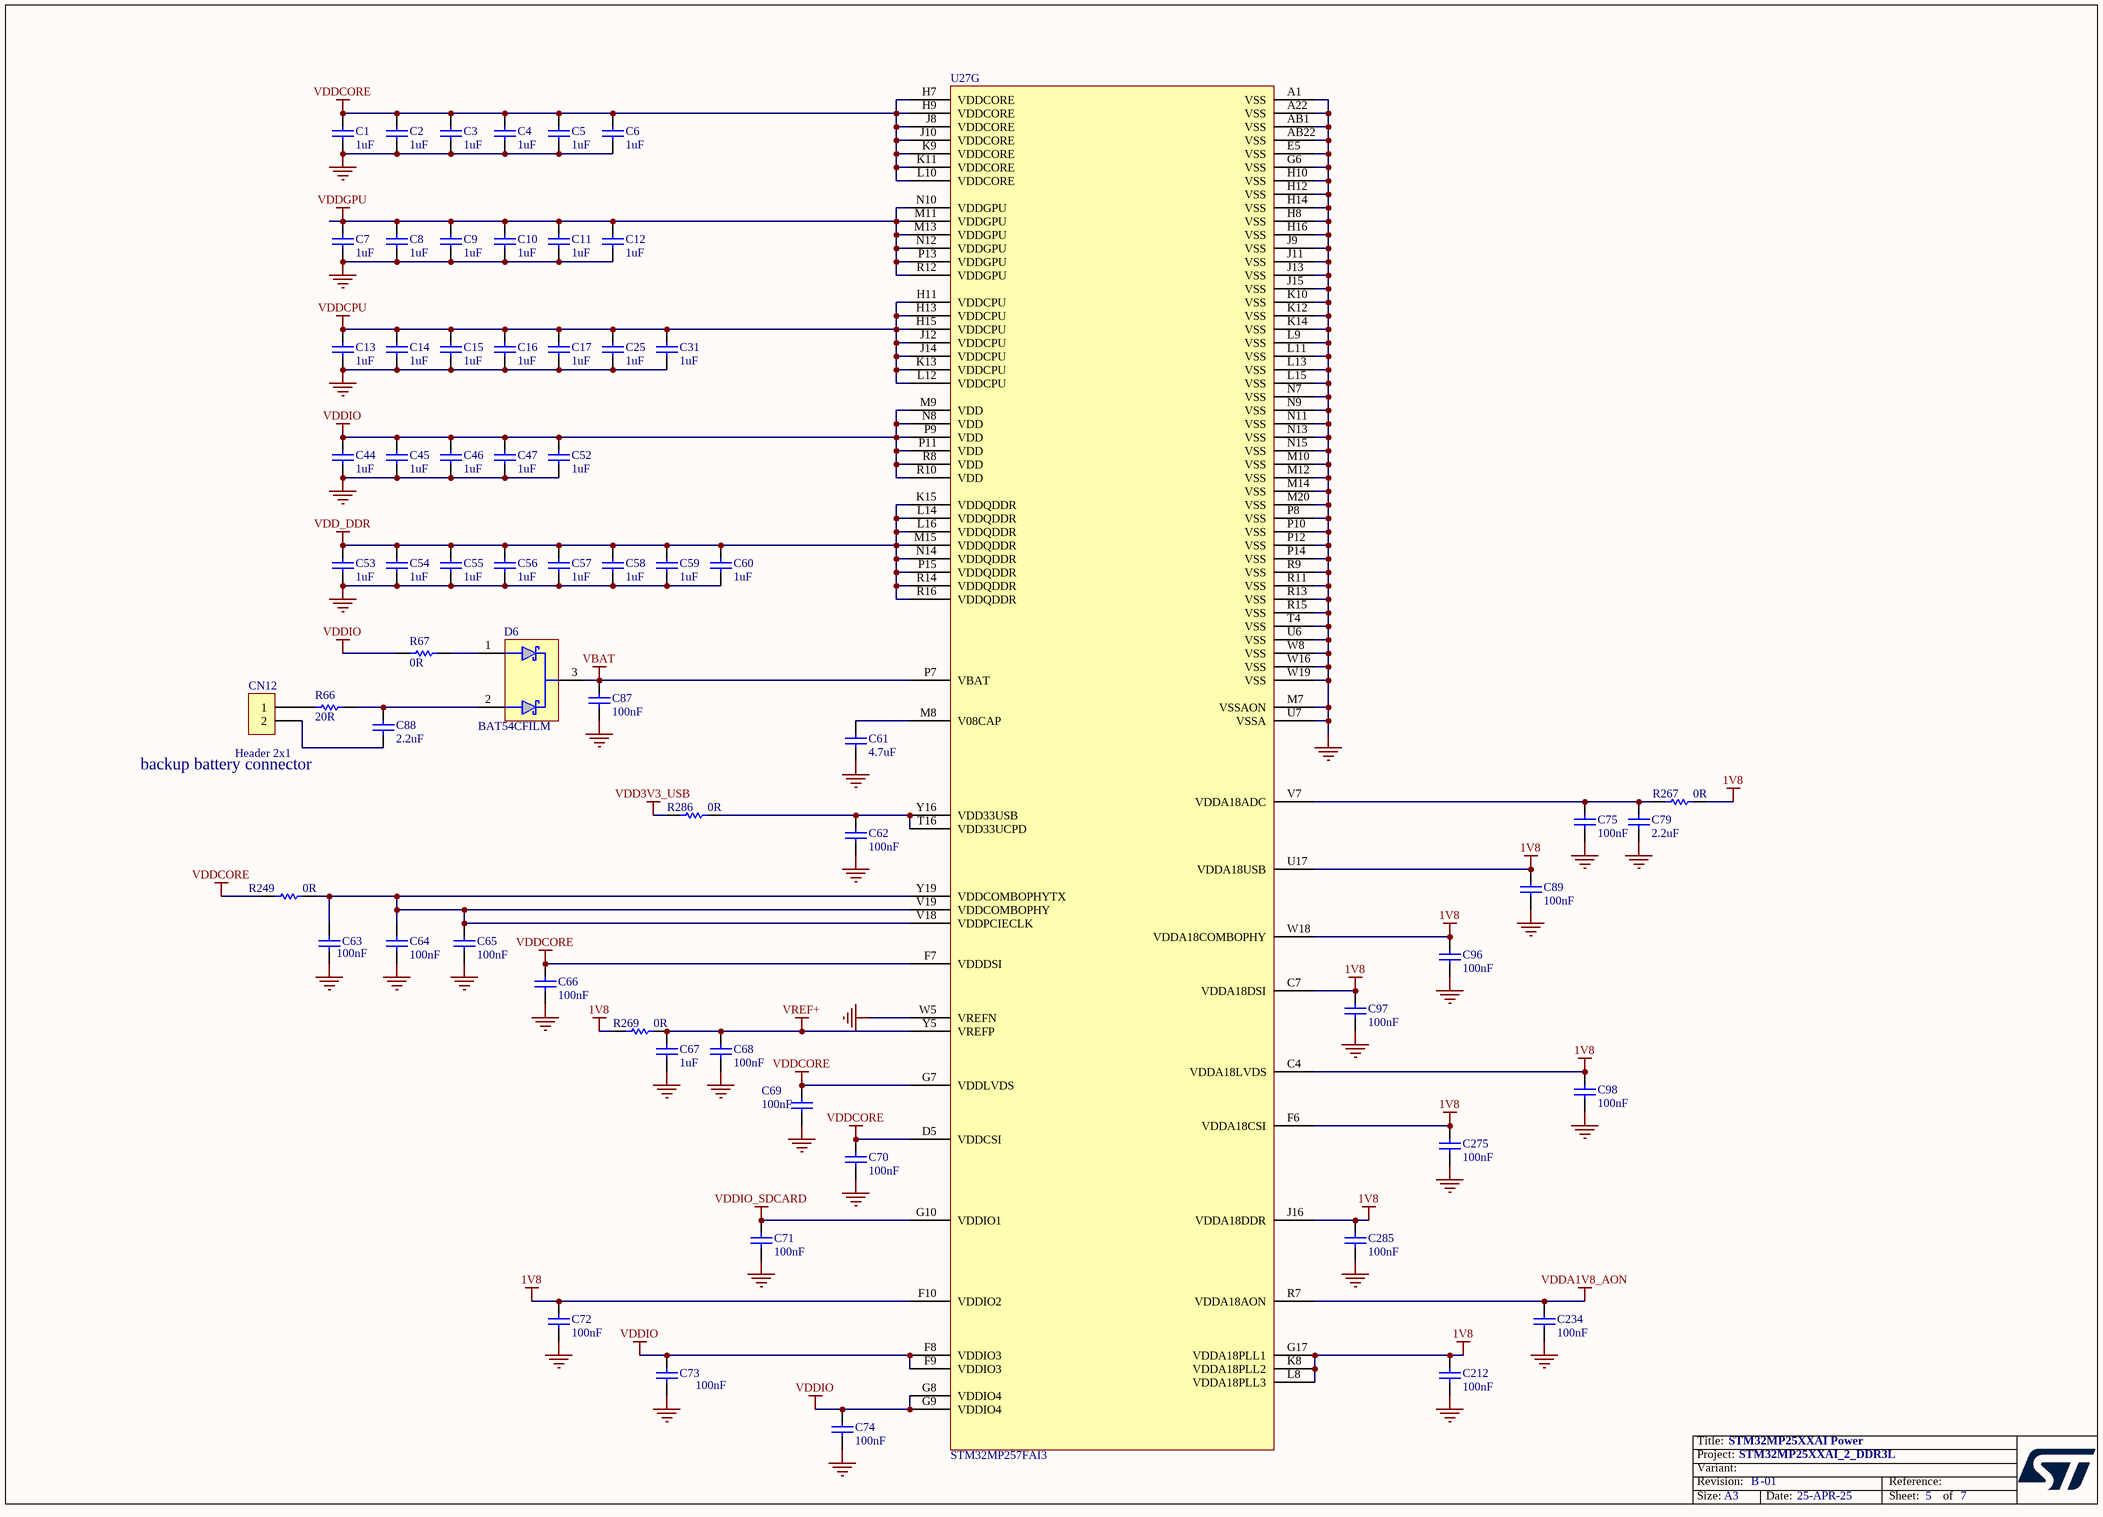
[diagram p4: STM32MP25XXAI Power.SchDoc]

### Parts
C1  value 1uF  [C0201_MURATA_GRM033_H0P3]  (hidden comment: Capacitor)
C2  value 1uF  [C0201_MURATA_GRM033_H0P3]  (hidden comment: Capacitor)
C3  value 1uF  [C0201_MURATA_GRM033_H0P3]  (hidden comment: Capacitor)
C4  value 1uF  [C0201_MURATA_GRM033_H0P3]  (hidden comment: Capacitor)
C5  value 1uF  [C0201_MURATA_GRM033_H0P3]  (hidden comment: Capacitor)
C6  value 1uF  [C0201_MURATA_GRM033_H0P3]  (hidden comment: Capacitor)
C7  value 1uF  [C0201_MURATA_GRM033_H0P3]  (hidden comment: Capacitor)
C8  value 1uF  [C0201_MURATA_GRM033_H0P3]  (hidden comment: Capacitor)
C9  value 1uF  [C0201_MURATA_GRM033_H0P3]  (hidden comment: Capacitor)
C10  value 1uF  [C0201_MURATA_GRM033_H0P3]  (hidden comment: Capacitor)
C11  value 1uF  [C0201_MURATA_GRM033_H0P3]  (hidden comment: Capacitor)
C12  value 1uF  [C0201_MURATA_GRM033_H0P3]  (hidden comment: Capacitor)
C13  value 1uF  [C0201_MURATA_GRM033_H0P3]  (hidden comment: Capacitor)
C14  value 1uF  [C0201_MURATA_GRM033_H0P3]  (hidden comment: Capacitor)
C15  value 1uF  [C0201_MURATA_GRM033_H0P3]  (hidden comment: Capacitor)
C16  value 1uF  [C0201_MURATA_GRM033_H0P3]  (hidden comment: Capacitor)
C17  value 1uF  [C0201_MURATA_GRM033_H0P3]  (hidden comment: Capacitor)
C25  value 1uF  [C0201_MURATA_GRM033_H0P3]  (hidden comment: Capacitor)
C31  value 1uF  [C0201_MURATA_GRM033_H0P3]  (hidden comment: Capacitor)
C44  value 1uF  [C0201_MURATA_GRM033_H0P3]  (hidden comment: Capacitor)
C45  value 1uF  [C0201_MURATA_GRM033_H0P3]  (hidden comment: Capacitor)
C46  value 1uF  [C0201_MURATA_GRM033_H0P3]  (hidden comment: Capacitor)
C47  value 1uF  [C0201_MURATA_GRM033_H0P3]  (hidden comment: Capacitor)
C52  value 1uF  [C0201_MURATA_GRM033_H0P3]  (hidden comment: Capacitor)
C53  value 1uF  [C0201_MURATA_GRM033_H0P3]  (hidden comment: Capacitor)
C54  value 1uF  [C0201_MURATA_GRM033_H0P3]  (hidden comment: Capacitor)
C55  value 1uF  [C0201_MURATA_GRM033_H0P3]  (hidden comment: Capacitor)
C56  value 1uF  [C0201_MURATA_GRM033_H0P3]  (hidden comment: Capacitor)
C57  value 1uF  [C0201_MURATA_GRM033_H0P3]  (hidden comment: Capacitor)
C58  value 1uF  [C0201_MURATA_GRM033_H0P3]  (hidden comment: Capacitor)
C59  value 1uF  [C0201_MURATA_GRM033_H0P3]  (hidden comment: Capacitor)
C60  value 1uF  [C0201_MURATA_GRM033_H0P3]  (hidden comment: Capacitor)
C61  value 4.7uF  [C0201_H0P5]  (hidden comment: Capacitor)
C62  value 100nF  [C0201_MURATA_GRM033_H0P3]  (hidden comment: Capacitor)
C63  value 100nF  [C0201_MURATA_GRM033_H0P3]  (hidden comment: Capacitor)
C64  value 100nF  [C0201_MURATA_GRM033_H0P3]  (hidden comment: Capacitor)
C65  value 100nF  [C0201_MURATA_GRM033_H0P3]  (hidden comment: Capacitor)
C66  value 100nF  [C0201_MURATA_GRM033_H0P3]  (hidden comment: Capacitor)
C67  value 1uF  [C0201_MURATA_GRM033_H0P3]  (hidden comment: Capacitor)
C68  value 100nF  [C0201_MURATA_GRM033_H0P3]  (hidden comment: Capacitor)
C69  value 100nF  [C0201_MURATA_GRM033_H0P3]  (hidden comment: Capacitor)
C70  value 100nF  [C0201_MURATA_GRM033_H0P3]  (hidden comment: Capacitor)
C71  value 100nF  [C0201_MURATA_GRM033_H0P3]  (hidden comment: Capacitor)
C72  value 100nF  [C0201_MURATA_GRM033_H0P3]  (hidden comment: Capacitor)
C73  value 100nF  [C0201_MURATA_GRM033_H0P3]  (hidden comment: Capacitor)
C74  value 100nF  [C0201_MURATA_GRM033_H0P3]  (hidden comment: Capacitor)
C75  value 100nF  [C0201_MURATA_GRM033_H0P3]  (hidden comment: Capacitor)
C79  value 2.2uF  [C0201_H0P5]  (hidden comment: Capacitor)
C87  value 100nF  [C0402]
C88  value 2.2uF  [C0402]  (hidden comment: Capacitor)
C89  value 100nF  [C0201_MURATA_GRM033_H0P3]  (hidden comment: Capacitor)
C96  value 100nF  [C0201_MURATA_GRM033_H0P3]  (hidden comment: Capacitor)
C97  value 100nF  [C0201_MURATA_GRM033_H0P3]  (hidden comment: Capacitor)
C98  value 100nF  [C0201_MURATA_GRM033_H0P3]  (hidden comment: Capacitor)
C212  value 100nF  [C0201_MURATA_GRM033_H0P3]  (hidden comment: Capacitor)
C234  value 100nF  [C0201_MURATA_GRM033_H0P3]  (hidden comment: Capacitor)
C275  value 100nF  [C0201_MURATA_GRM033_H0P3]  (hidden comment: Capacitor)
C285  value 100nF  [C0201_MURATA_GRM033_H0P3]  (hidden comment: Capacitor)
CN12  value Header 2x1  [CON_MOLEX_53047-0210]
D6  value BAT54CFILM  [DIO_SOT23]  (hidden comment: DIODE_3P_DUAL_COMMON_CATHODE)
R66  value 20R  [R0402]  (hidden comment: Resistor)
R67  value 0R  [R0402]  (hidden comment: Resistor)
R249  value 0R  [R0603]  (hidden comment: Resistor)
R267  value 0R  [R0402]
R269  value 0R  [R0402]
R286  value 0R  [R0402]
U27  STM32MP257FAI3  [ICC_LFBGA436_18X18_P080_H1P70_STM32MP257_CODE-B0D1]  (part G of 9)

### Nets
1V8: C72.2 C89.2 C96.2 C97.2 C98.2 C212.2 C275.2 C285.2 R267.2 R269.1 U27.C4(VDDA18LVDS) U27.C7(VDDA18DSI) U27.F6(VDDA18CSI) U27.F10(VDDIO2) U27.G17(VDDA18PLL1) U27.J16(VDDA18DDR) U27.K8(VDDA18PLL2) U27.L8(VDDA18PLL3) U27.U17(VDDA18USB) U27.W18(VDDA18COMBOPHY)
GND: C1.2 C2.1 C3.1 C4.2 C5.1 C6.1 C7.1 C8.1 C9.1 C10.1 C11.2 C12.1 C13.2 C14.1 C15.1 C16.2 C17.1 C25.1 C31.1 C44.2 C45.1 C46.1 C47.2 C52.1 C53.1 C54.2 C55.1 C56.1 C57.1 C58.1 C59.1 C60.1 C61.1 C62.1 C63.1 C64.1 C65.1 C66.1 C67.1 C68.1 C69.1 C70.1 C71.1 C72.1 C73.1 C74.1 C75.1 C79.1 C87.1 C89.1 C96.1 C97.1 C98.1 C212.1 C234.1 C275.1 C285.1 U27.A1(VSS) U27.A22(VSS) U27.AB1(VSS) U27.AB22(VSS) U27.E5(VSS) U27.G6(VSS) U27.H8(VSS) U27.H10(VSS) U27.H12(VSS) U27.H14(VSS) U27.H16(VSS) U27.J9(VSS) U27.J11(VSS) U27.J13(VSS) U27.J15(VSS) U27.K10(VSS) U27.K12(VSS) U27.K14(VSS) U27.L9(VSS) U27.L11(VSS) U27.L13(VSS) U27.L15(VSS) U27.M7(VSSAON) U27.M10(VSS) U27.M12(VSS) U27.M14(VSS) U27.M20(VSS) U27.N7(VSS) U27.N9(VSS) U27.N11(VSS) U27.N13(VSS) U27.N15(VSS) U27.P8(VSS) U27.P10(VSS) U27.P12(VSS) U27.P14(VSS) U27.R9(VSS) U27.R11(VSS) U27.R13(VSS) U27.R15(VSS) U27.T4(VSS) U27.U6(VSS) U27.U7(VSSA) U27.W5(VREFN) U27.W8(VSS) U27.W16(VSS) U27.W19(VSS)
VBAT: C87.2 D6.3 U27.P7(VBAT)
VDD3V3_USB: R286.1
VDD_DDR: C53.2 C54.1 C55.2 C56.2 C57.2 C58.2 C59.2 C60.2 U27.K15(VDDQDDR) U27.L14(VDDQDDR) U27.L16(VDDQDDR) U27.M15(VDDQDDR) U27.N14(VDDQDDR) U27.P15(VDDQDDR) U27.R14(VDDQDDR) U27.R16(VDDQDDR)
VDDA1V8_AON: C234.2 U27.R7(VDDA18AON)
VDDCORE: C1.1 C2.2 C3.2 C4.1 C5.2 C6.2 C66.2 C69.2 C70.2 R249.1 U27.D5(VDDCSI) U27.F7(VDDDSI) U27.G7(VDDLVDS) U27.H7(VDDCORE) U27.H9(VDDCORE) U27.J8(VDDCORE) U27.J10(VDDCORE) U27.K9(VDDCORE) U27.K11(VDDCORE) U27.L10(VDDCORE)
VDDCPU: C13.1 C14.2 C15.2 C16.1 C17.2 C25.2 C31.2 U27.H11(VDDCPU) U27.H13(VDDCPU) U27.H15(VDDCPU) U27.J12(VDDCPU) U27.J14(VDDCPU) U27.K13(VDDCPU) U27.L12(VDDCPU)
VDDGPU: C7.2 C8.2 C9.2 C10.2 C11.1 C12.2 U27.M11(VDDGPU) U27.M13(VDDGPU) U27.N10(VDDGPU) U27.N12(VDDGPU) U27.P13(VDDGPU) U27.R12(VDDGPU)
VDDIO: C44.1 C45.2 C46.2 C47.1 C52.2 C73.2 C74.2 R67.2 U27.F8(VDDIO3) U27.F9(VDDIO3) U27.G8(VDDIO4) U27.G9(VDDIO4) U27.M9(VDD) U27.N8(VDD) U27.P9(VDD) U27.P11(VDD) U27.R8(VDD) U27.R10(VDD)
VDDIO_SDCARD: C71.2 U27.G10(VDDIO1)
VREF+: C67.2 C68.2 R269.2 U27.Y5(VREFP)
NetC61_2: C61.2 U27.M8(V08CAP)
NetC62_2: C62.2 R286.2 U27.T16(VDD33UCPD) U27.Y16(VDD33USB)
NetC63_2: C63.2 C64.2 C65.2 R249.2 U27.V18(VDDPCIECLK) U27.V19(VDDCOMBOPHY) U27.Y19(VDDCOMBOPHYTX)
NetC75_2: C75.2 C79.2 R267.1 U27.V7(VDDA18ADC)
NetC88_1: C88.1 CN12.2
NetC88_2: C88.2 D6.2 R66.2
NetCN12_1: CN12.1 R66.1
NetD6_1: D6.1 R67.1

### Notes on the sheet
- backup battery connector

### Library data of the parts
C1-C17 C25 C31 C44-C47 C52-C60 C67 = MCD-02377: Capacitor, MLCC, 1uF, 6.3V, X5R, +/-20%, 0201, T=0,3mm; Manufacturer_Part_Number: GRM033R60J105MEA2; Manufacturer: MURATA; Part_Preference: Recommended; Order_Code_RS: 820-0643; Component_Country_Of_Origin: Japan°; ID: 4483; ShowFields: YES
C61 = MCD-01534: Capacitor, MLCC, 4,7uF, 6V3, X5R, +/-20%, 0201, T=0.5mm; Part_Preference: Recommended; Manufacturer: MURATA; Manufacturer_Part_Number: GRM035R60J475ME15; Component_Country_Of_Origin: Japan°°; ID: 3634; ShowFields: YES
C62-C66 C68-C75 C89 C96-C98 C212 C234 C275 C285 = MCD-01535: Capacitor, MLCC,100nF, 10V, X7R, +/-10%, 0201, T=0.3mm; Part_Preference: Recommended; Manufacturer: MURATA; Manufacturer_Part_Number: GRM033R61A104KE15; Order_Code_RS: 790-2742; Component_Country_Of_Origin: Japan°°; ID: 3635; ShowFields: YES
C79 = MCD-02235: Capacitor, MLCC, 2.2uF, 10V, X5R,+/-10%, 0201, T=0.5mm; Part_Preference: Recommended; Manufacturer: MURATA; Manufacturer_Part_Number: GRM033R61A225KE47D; Order_Code_RS: NA; Component_Country_Of_Origin: Japan°°; ShowFields: YES; ID: 4335
C87 = MCD-00006: Capacitor,100nF,16V,X7R,10%,0402; Manufacturer_Part_Number: CC0402KRX7R7BB104; Manufacturer: YAGEO; Alternate_Manufacturer: MURATA; Alternate_Manufacturer_Part_Number: GCM155R71C104KA55D; Part_Preference: Recommended; Partial_Alternate_Internal_Part_Number: MCD-03299; Provided_By: SUBCO; Initial_Board_Reference: MB1274; Order_Code_RS: 9402047; Component_Country_Of_Origin: China; ID: 2474; ShowFields: YES
C88 = MCD-01823: Capacitor, MLCC, 2.2uF, 6V3, X5R,+/-10%, 0402, T=0.5mm; Part_Preference: Recommended; Manufacturer: MURATA; Manufacturer_Part_Number: GRM155R60J225KE95D; Partial_Alternate_Internal_Part_Number: MCD-03566; Order_Code_RS: 172-6478; Component_Country_Of_Origin: Japan°°; ID: 3923; ShowFields: YES
CN12 = MCD-00655: Header 2 circuits, 1.25mm Pitch ,  Vertical, with Friction Lock; Part_Type: Connector; Manufacturer_Part_Number: 53047-0210; Manufacturer: MOLEX; BMS_Part_Number: 9083002; Part_Preference: Recommended; Provided_By: SUBCO; Initial_Board_Reference: MB1272; Order_Code_RS: 279-9213; Component_Country_Of_Origin: Unknown; ID: 3091; ShowFields: YES
D6 = MCD-03280: Diode, Schottky, Dual Common Cathode, 0V3, 300mA, 40V, SOT-23; Part_Preference: Recommended; Manufacturer: STMICROELECTRONICS; Order_code_RS: 795-8397; Component_Country_Of_Origin: China; ShowFields: YES; ID: 5396
R66 = MCD-00058: Resistor, 20R, 0402, +/-1%, 1/16W; BMS_Part_Number: 9131027; Part_Preference: Recommended; Manufacturer: YAGEO; Manufacturer_Part_Number: RC0402FR-0720RL; Order_Code_RS: 1799192; Component_Country_Of_Origin: China; ID: 2537; ShowFields: YES
R67 = MCD-00052: Resistor, 0R, 0402, +/-5%, 1/16W; Manufacturer_Part_Number: RC0402JR-070RL; Manufacturer: YAGEO; Part_Preference: Recommended; Order_Code_RS: 9232516RL; Component_Country_Of_Origin: China; ShowFields: YES; ID: 2540
R249 = MCD-00056: Resistor, 0R, 0603, +/-5%, 1/10W; Part_Preference: Recommended; Manufacturer: YAGEO; Manufacturer_Part_Number: RC0603JR-070RL; Order_Code_RS: 9233130RL; Component_Country_Of_Origin: China; ShowFields: YES; ID: 2536
R267 R269 R286 = MCD-00052: as R2 on sheet PMIC
U27 = MCD-02000: as U27 on sheet STM32MP25XXAI I_Os

## Sheet eMMC.SchDoc: eMMC
size A3; Date: Not used; ApprovedBy: Not used; CheckedBy: Not used; Author: Not used; CompanyName: STMicroelectronics; DrawnBy: Not used; Engineer: Not used; Organization: Not used; Address1: Not used; Address2: Not used; Address3: Not used; Address4: Not used; DocumentNumber: 7; Revision: Not used; SheetNumber: 7; SheetTotal: 7
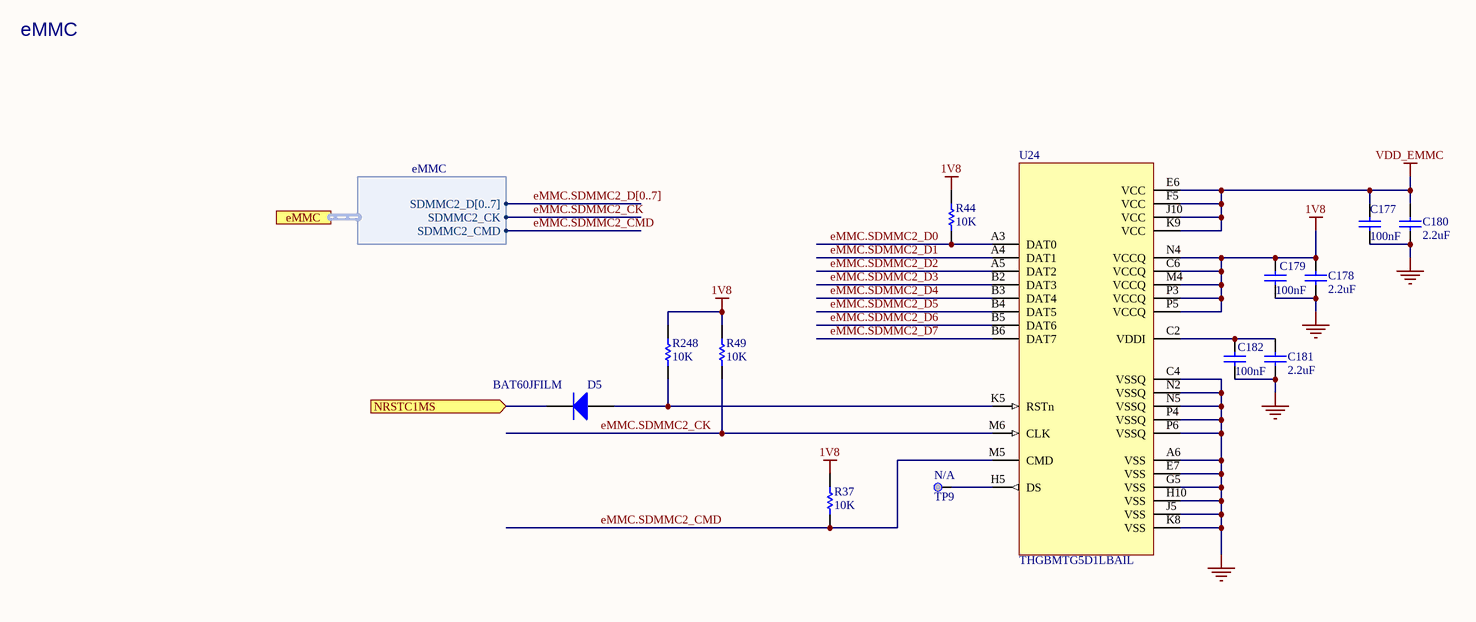
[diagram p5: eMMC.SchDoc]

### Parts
C177  value 100nF  [C0402]  (hidden comment: Capacitor)
C178  value 2.2uF  [C0402]  (hidden comment: Capacitor)
C179  value 100nF  [C0402]  (hidden comment: Capacitor)
C180  value 2.2uF  [C0402]  (hidden comment: Capacitor)
C181  value 2.2uF  [C0402]  (hidden comment: Capacitor)
C182  value 100nF  [C0402]  (hidden comment: Capacitor)
D5  BAT60JFILM  [DIO_SOD323]
R37  value 10K  [R0402]  (hidden comment: Resistor)
R44  value 10K  [R0402]  (hidden comment: Resistor)
R49  value 10K  [R0402]  (hidden comment: Resistor)
R248  value 10K  [R0402]  (hidden comment: Resistor)
TP9  Test Point  [TP_SMD_1MM]  (value not drawn)  (no BOM)
U24  value THGBMTG5D1LBAIL  [ICC_P-WFBGA153_13X11P5_P050]  (hidden comment: eMMC_THGBMTG5D1LBAIL)

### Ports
eMMC (harness eMMC), NRSTC1MS (in)

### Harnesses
eMMC: SDMMC2_CK, SDMMC2_CMD, SDMMC2_D[0..7]

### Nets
1V8: C178.2 C179.2 R37.2 R44.2 R49.2 R248.2 U24.C6(VCCQ) U24.M4(VCCQ) U24.N4(VCCQ) U24.P3(VCCQ) U24.P5(VCCQ)
GND: C177.1 C178.1 C179.1 C180.1 C181.1 C182.1 U24.A6(VSS) U24.C4(VSSQ) U24.E7(VSS) U24.G5(VSS) U24.H10(VSS) U24.J5(VSS) U24.K8(VSS) U24.N2(VSSQ) U24.N5(VSSQ) U24.P4(VSSQ) U24.P6(VSSQ)
VDD_EMMC: C177.2 C180.2 U24.E6(VCC) U24.F5(VCC) U24.J10(VCC) U24.K9(VCC)
eMMC.SDMMC2_CK: R49.1 U24.M6(CLK) ; port eMMC.SDMMC2_CK
eMMC.SDMMC2_CMD: R37.1 U24.M5(CMD) ; port eMMC.SDMMC2_CMD
eMMC.SDMMC2_D0: R44.1 U24.A3(DAT0)
eMMC.SDMMC2_D1: U24.A4(DAT1)
eMMC.SDMMC2_D2: U24.A5(DAT2)
eMMC.SDMMC2_D3: U24.B2(DAT3)
eMMC.SDMMC2_D4: U24.B3(DAT4)
eMMC.SDMMC2_D5: U24.B4(DAT5)
eMMC.SDMMC2_D6: U24.B5(DAT6)
eMMC.SDMMC2_D7: U24.B6(DAT7)
NRSTC1MS: D5.2(K) ; port NRSTC1MS
NetC181_2: C181.2 C182.2 U24.C2(VDDI)
NetD5_1: D5.1(A) R248.1 U24.K5(RSTn)
NetTP9_1: TP9.1 U24.H5(DS)

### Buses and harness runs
bus eMMC.SDMMC2_D[0..7]

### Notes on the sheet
- eMMC

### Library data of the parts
C177 C179 C182 = MCD-00006: Capacitor, MLCC, 100nF, 16V, X7R, +/-10%, 0402, T=0.5mm; Part_Preference: Recommended; Manufacturer: YAGEO; Manufacturer_Part_Number: CC0402KRX7R7BB104; Alternate_Manufacturer: MURATA; Alternate_Manufacturer_Part_Number: GCM155R71C104KA55D; Partial_Alternate_Internal_Part_Number: MCD-03299; Order_Code_RS: 9402047; Component_Country_Of_Origin: China; ID: 2474; ShowFields: YES
C178 C180 C181 = MCD-02606: Capacitor, MLCC, 2.2uF, 6.3V, X5R, +/-10%, 0402, T=0.5mm; Part_Preference: Recommended; Manufacturer: YAGEO; Manufacturer_Part_Number: CC0402KRX5R5BB225; Order_Code_RS: 1992205; ShowFields: YES; ID: 4712; Component_Country_Of_Origin: China°
D5 = MCD-00034: BMS_Part_Number: 9151097; Part_Type: Diode; Part_Preference: Recommended; Manufacturer: STMICROELECTRONICS; Manufacturer_HQ_COO: EU; Component_Country_Of_Origin: China; ShowFields: YES; ID: 2483; Order_Code_RS: 714-6879
R37 R44 R49 R248 = MCD-00053: Resistor,10K,0402,1%,1/16W; Manufacturer_Part_Number: RC0402FR-0710KL; Manufacturer: YAGEO; BMS_Part_Number: 9131590; Part_Preference: Recommended; ECCN_US: EAR99; ECCN_EU: NEC; Provided_By: SUBCO; Order_Code_RS: 9239359; Component_Country_Of_Origin: China; ID: 2539; ShowFields: YES
TP9 = MCD-00074: Test Point 1mm; Part_Type: Misc; Part_Preference: Recommended; Component_Country_Of_Origin: Unknown; ID: 2518; ShowFields: YES
U24 = MCD-02799: Memory, eMMC, 4GB, 15nm ,WFBGA , 153 pins; Part_Type: IC; Part_Preference: Not recommended; Manufacturer: KIOXIA; ShowFields: YES; ID: 4911; Component_Country_Of_Origin: Unknown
